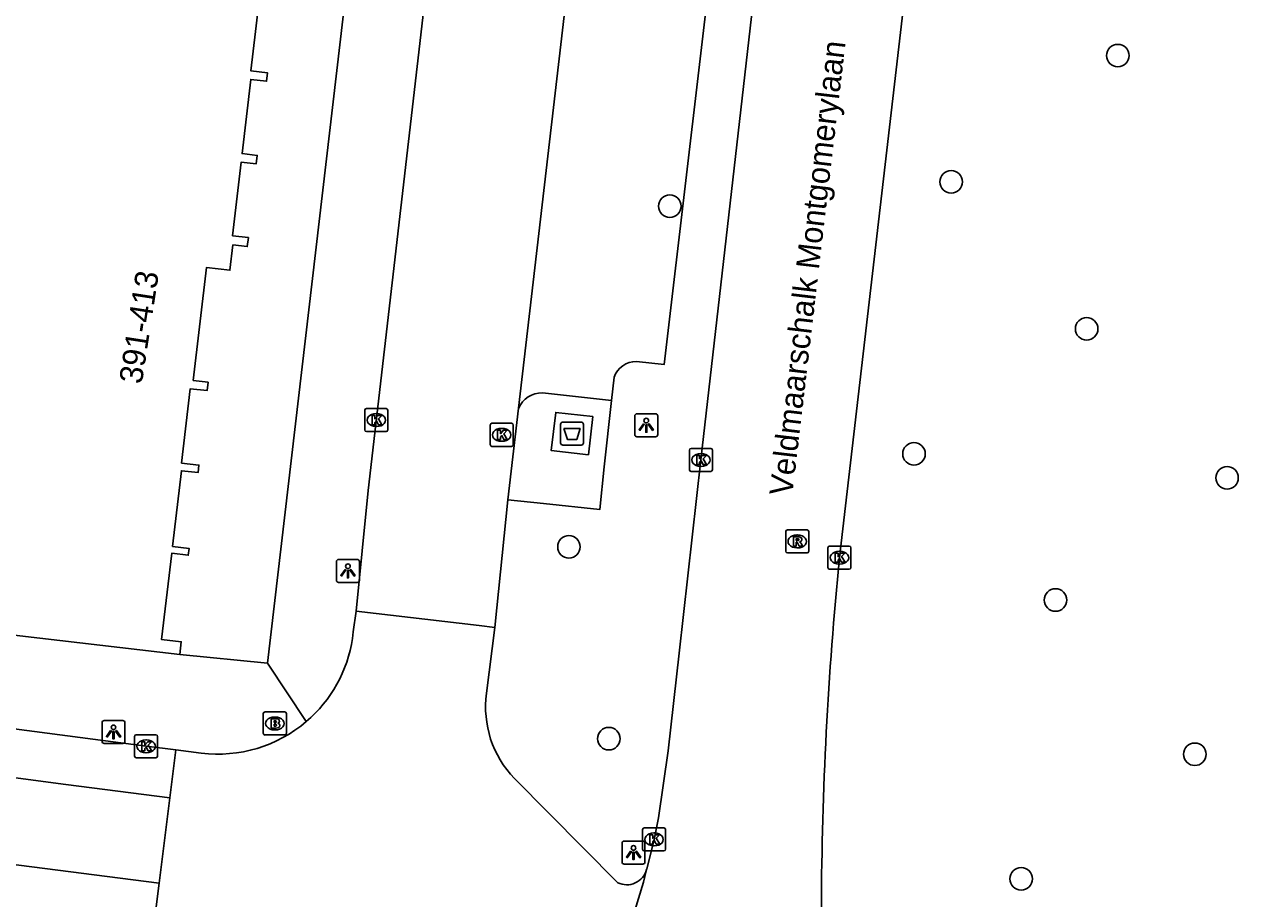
# Model space of a CAD drawing. Extents: x 160861 to 161308, y 384024 to 384878.
# Drawn here: x 161210.2 to 161263.2, y 384371.9 to 384409.8 of the extents above; entities that cross this region are included whole.
import ezdxf

# ---------------------------------------------------------------- set-up
doc = ezdxf.new("R2010")
doc.units = 0
for name, color, linetype in [('IMGEO_Afval_apart_plaats', 7, 'Continuous'), ('IMGEO_Boom', 7, 'Continuous'), ('IMGEO_Brandkraan', 7, 'Continuous'), ('IMGEO_Kolk', 7, 'Continuous'), ('IMGEO_Lichtpunt', 7, 'Continuous'), ('IMGEO_Openbare_ruimte_label', 7, 'Continuous'), ('IMGEO_Pand', 7, 'Continuous'), ('IMGEO_Pand_nummerreeks', 7, 'Continuous'), ('IMGEO_Parkeervlak_open', 7, 'Continuous'), ('IMGEO_Rijbaan_lokaal_gesloten', 7, 'Continuous'), ('IMGEO_Rijbaan_lokaal_open', 7, 'Continuous'), ('IMGEO_Rioolput', 7, 'Continuous'), ('IMGEO_Voetpad_gesloten', 7, 'Continuous'), ('IMGEO_Voetpad_open', 7, 'Continuous')]:
    doc.layers.add(name, color=color, linetype=linetype)

msp = doc.modelspace()

# ---------------------------------------------------------------- linework, layer by layer
at = {"layer": 'IMGEO_Afval_apart_plaats'}
for p, q in [((161233.508, 384391.639), (161233.508, 384392.439)), ((161233.508, 384392.439), (161233.508, 384391.639)), ((161233.608, 384392.539), (161234.398, 384392.539)), ((161234.398, 384392.539), (161233.608, 384392.539)), ((161234.498, 384392.439), (161234.498, 384391.639)), ((161234.498, 384391.639), (161234.498, 384392.439)), ((161234.398, 384391.539), (161233.608, 384391.539)), ((161233.608, 384391.539), (161234.398, 384391.539))]:
    msp.add_line(p, q, dxfattribs=at)
msp.add_lwpolyline([(161233.651, 384392.253), (161234.355, 384392.253), (161234.206, 384391.783), (161233.8, 384391.783), (161233.651, 384392.253)], dxfattribs=at)
for centre, start, end in [((161233.608, 384392.439), 90, 180), ((161233.608, 384392.439), 90, 180), ((161234.398, 384392.439), 0, 90), ((161234.398, 384392.439), 360, 90), ((161233.608, 384391.639), 180, 270), ((161233.608, 384391.639), 180, 270), ((161234.398, 384391.639), 270, 0), ((161234.398, 384391.639), 270, 0)]:
    msp.add_arc(centre, 0.1, start, end, dxfattribs=at)
at = {"layer": 'IMGEO_Boom'}
for centre in [(161257.691, 384408.433), (161250.463, 384402.957), (161238.248, 384401.904), (161256.341, 384396.581), (161248.846, 384391.156), (161262.436, 384390.118), (161233.869, 384387.13), (161254.991, 384384.819), (161235.599, 384378.804), (161261.035, 384378.127), (161253.501, 384372.726)]:
    msp.add_circle(centre, 0.489, dxfattribs=at)
at = {"layer": 'IMGEO_Brandkraan'}
for p, q in [((161220.602, 384379.038), (161220.602, 384379.89)), ((161220.677, 384379.964), (161221.529, 384379.964)), ((161221.09, 384379.744), (161221.115, 384379.744)), ((161221.603, 384379.89), (161221.603, 384379.038)), ((161221.113, 384379.184), (161221.088, 384379.184)), ((161221.529, 384378.964), (161220.677, 384378.964))]:
    msp.add_line(p, q, dxfattribs=at)
for points in [[(161220.602, 384379.038), (161220.602, 384379.89)], [(161220.677, 384379.964), (161221.529, 384379.964)], [(161220.95, 384379.664), (161220.95, 384379.264), (161221.163, 384379.264)], [(161221.181, 384379.664), (161220.95, 384379.664)], [(161221.129, 384379.583), (161221.075, 384379.583), (161221.075, 384379.507)], [(161221.603, 384379.89), (161221.603, 384379.038)], [(161221.075, 384379.507), (161221.128, 384379.507)], [(161221.137, 384379.431), (161221.075, 384379.431), (161221.075, 384379.35)], [(161221.075, 384379.35), (161221.137, 384379.35)], [(161221.529, 384378.964), (161220.677, 384378.964)]]:
    msp.add_lwpolyline(points, dxfattribs=at)
for centre, radius, start, end in [((161220.679, 384379.888), 0.0765, 91.552, 178.448), ((161220.679, 384379.888), 0.0765, 91.552, 178.448), ((161221.13, 384379.545), 0.0379, 267.8285, 90.9355), ((161221.185, 384379.519), 0.145, 59.4692, 91.5367), ((161221.21, 384379.566), 0.0922, 285.5137, 58.1501), ((161221.527, 384379.888), 0.0765, 1.552, 88.448), ((161221.527, 384379.888), 0.0765, 1.552, 88.448), ((161220.679, 384379.04), 0.0765, 181.552, 268.448), ((161220.679, 384379.04), 0.0765, 181.552, 268.448), ((161221.138, 384379.39), 0.0404, 269.8759, 90.5077), ((161221.169, 384379.515), 0.251, 268.6676, 293.5347), ((161221.215, 384379.374), 0.105, 301.3115, 78.989), ((161221.527, 384379.04), 0.0765, 271.552, 358.448), ((161221.527, 384379.04), 0.0765, 271.552, 358.448)]:
    msp.add_arc(centre, radius, start, end, dxfattribs=at)
for centre, major_axis, ratio, start_param, end_param in [((161221.089, 384379.464), (-0.387, 0.002), 0.722429, 4.712389, 7.853982), ((161221.114, 384379.464), (-0.39, 0.002), 0.717154, 1.570796, 4.712389)]:
    msp.add_ellipse(centre, major_axis=major_axis, ratio=ratio, start_param=start_param, end_param=end_param, dxfattribs=at)
at = {"layer": 'IMGEO_Kolk'}
for p, q in [((161225.006, 384392.198), (161225.006, 384393.05)), ((161225.081, 384393.124), (161225.933, 384393.124)), ((161225.494, 384392.904), (161225.519, 384392.904)), ((161226.007, 384393.05), (161226.007, 384392.198)), ((161225.517, 384392.344), (161225.492, 384392.344)), ((161230.449, 384391.558), (161230.449, 384392.41)), ((161230.524, 384392.484), (161231.376, 384392.484)), ((161230.937, 384392.264), (161230.962, 384392.264)), ((161231.45, 384392.41), (161231.45, 384391.558)), ((161225.933, 384392.124), (161225.081, 384392.124)), ((161230.96, 384391.704), (161230.935, 384391.704)), ((161231.376, 384391.484), (161230.524, 384391.484)), ((161239.099, 384390.468), (161239.099, 384391.32)), ((161239.174, 384391.394), (161240.026, 384391.394)), ((161239.587, 384391.174), (161239.612, 384391.174)), ((161240.1, 384391.32), (161240.1, 384390.468)), ((161240.026, 384390.394), (161239.174, 384390.394)), ((161239.61, 384390.614), (161239.585, 384390.614)), ((161245.11, 384386.23), (161245.11, 384387.082)), ((161245.185, 384387.156), (161246.037, 384387.156)), ((161246.111, 384387.082), (161246.111, 384386.23)), ((161245.598, 384386.936), (161245.623, 384386.936)), ((161246.037, 384386.156), (161245.185, 384386.156)), ((161245.621, 384386.376), (161245.596, 384386.376)), ((161215.013, 384378.048), (161215.013, 384378.9)), ((161215.088, 384378.974), (161215.94, 384378.974)), ((161215.501, 384378.754), (161215.526, 384378.754)), ((161216.014, 384378.9), (161216.014, 384378.048)), ((161215.94, 384377.974), (161215.088, 384377.974)), ((161215.524, 384378.194), (161215.499, 384378.194)), ((161237.062, 384374.008), (161237.062, 384374.86)), ((161237.137, 384374.934), (161237.989, 384374.934)), ((161238.063, 384374.86), (161238.063, 384374.008)), ((161237.55, 384374.714), (161237.575, 384374.714)), ((161237.989, 384373.934), (161237.137, 384373.934)), ((161237.573, 384374.154), (161237.548, 384374.154))]:
    msp.add_line(p, q, dxfattribs=at)
for points in [[(161225.006, 384392.198), (161225.006, 384393.05)], [(161225.081, 384393.124), (161225.933, 384393.124)], [(161225.327, 384392.824), (161225.45, 384392.824), (161225.45, 384392.673), (161225.58, 384392.824), (161225.744, 384392.824), (161225.598, 384392.673), (161225.751, 384392.424), (161225.599, 384392.424), (161225.514, 384392.588), (161225.45, 384392.521), (161225.45, 384392.424), (161225.327, 384392.424), (161225.327, 384392.824)], [(161226.007, 384393.05), (161226.007, 384392.198)], [(161230.449, 384391.558), (161230.449, 384392.41)], [(161230.524, 384392.484), (161231.376, 384392.484)], [(161231.45, 384392.41), (161231.45, 384391.558)], [(161225.933, 384392.124), (161225.081, 384392.124)], [(161230.77, 384392.184), (161230.893, 384392.184), (161230.893, 384392.033), (161231.023, 384392.184), (161231.187, 384392.184), (161231.041, 384392.033), (161231.194, 384391.784), (161231.042, 384391.784), (161230.957, 384391.948), (161230.893, 384391.881), (161230.893, 384391.784), (161230.77, 384391.784), (161230.77, 384392.184)], [(161231.376, 384391.484), (161230.524, 384391.484)], [(161239.099, 384390.468), (161239.099, 384391.32)], [(161239.174, 384391.394), (161240.026, 384391.394)], [(161240.1, 384391.32), (161240.1, 384390.468)], [(161239.42, 384391.094), (161239.543, 384391.094), (161239.543, 384390.943), (161239.673, 384391.094), (161239.837, 384391.094), (161239.691, 384390.943), (161239.844, 384390.694), (161239.692, 384390.694), (161239.607, 384390.858), (161239.543, 384390.791), (161239.543, 384390.694), (161239.42, 384390.694), (161239.42, 384391.094)], [(161240.026, 384390.394), (161239.174, 384390.394)], [(161245.11, 384386.23), (161245.11, 384387.082)], [(161245.185, 384387.156), (161246.037, 384387.156)], [(161246.111, 384387.082), (161246.111, 384386.23)], [(161245.431, 384386.856), (161245.554, 384386.856), (161245.554, 384386.705), (161245.684, 384386.856), (161245.848, 384386.856), (161245.702, 384386.705), (161245.855, 384386.456), (161245.703, 384386.456), (161245.618, 384386.62), (161245.554, 384386.553), (161245.554, 384386.456), (161245.431, 384386.456), (161245.431, 384386.856)], [(161246.037, 384386.156), (161245.185, 384386.156)], [(161215.013, 384378.048), (161215.013, 384378.9)], [(161215.088, 384378.974), (161215.94, 384378.974)], [(161215.334, 384378.674), (161215.457, 384378.674), (161215.457, 384378.523), (161215.587, 384378.674), (161215.751, 384378.674), (161215.605, 384378.523), (161215.758, 384378.274), (161215.606, 384378.274), (161215.521, 384378.438), (161215.457, 384378.371), (161215.457, 384378.274), (161215.334, 384378.274), (161215.334, 384378.674)], [(161216.014, 384378.9), (161216.014, 384378.048)], [(161215.94, 384377.974), (161215.088, 384377.974)], [(161237.062, 384374.008), (161237.062, 384374.86)], [(161237.137, 384374.934), (161237.989, 384374.934)], [(161238.063, 384374.86), (161238.063, 384374.008)], [(161237.383, 384374.634), (161237.506, 384374.634), (161237.506, 384374.483), (161237.636, 384374.634), (161237.8, 384374.634), (161237.654, 384374.483), (161237.807, 384374.234), (161237.655, 384374.234), (161237.57, 384374.398), (161237.506, 384374.331), (161237.506, 384374.234), (161237.383, 384374.234), (161237.383, 384374.634)], [(161237.989, 384373.934), (161237.137, 384373.934)]]:
    msp.add_lwpolyline(points, dxfattribs=at)
for centre, start, end in [((161225.083, 384393.048), 91.552, 178.448), ((161225.083, 384393.048), 91.552, 178.448), ((161225.931, 384393.048), 1.552, 88.448), ((161225.931, 384393.048), 1.552, 88.448), ((161230.526, 384392.408), 91.552, 178.448), ((161230.526, 384392.408), 91.552, 178.448), ((161231.374, 384392.408), 1.552, 88.448), ((161231.374, 384392.408), 1.552, 88.448), ((161225.083, 384392.2), 181.552, 268.448), ((161225.083, 384392.2), 181.552, 268.448), ((161225.931, 384392.2), 271.552, 358.448), ((161225.931, 384392.2), 271.552, 358.448), ((161230.526, 384391.56), 181.552, 268.448), ((161230.526, 384391.56), 181.552, 268.448), ((161231.374, 384391.56), 271.552, 358.448), ((161231.374, 384391.56), 271.552, 358.448), ((161239.176, 384391.318), 91.552, 178.448), ((161239.176, 384391.318), 91.552, 178.448), ((161240.024, 384391.318), 1.552, 88.448), ((161240.024, 384391.318), 1.552, 88.448), ((161239.176, 384390.47), 181.552, 268.448), ((161239.176, 384390.47), 181.552, 268.448), ((161240.024, 384390.47), 271.552, 358.448), ((161240.024, 384390.47), 271.552, 358.448), ((161245.187, 384387.08), 91.552, 178.448), ((161245.187, 384387.08), 91.552, 178.448), ((161246.035, 384387.08), 1.552, 88.448), ((161246.035, 384387.08), 1.552, 88.448), ((161245.187, 384386.232), 181.552, 268.448), ((161245.187, 384386.232), 181.552, 268.448), ((161246.035, 384386.232), 271.552, 358.448), ((161246.035, 384386.232), 271.552, 358.448), ((161215.09, 384378.898), 91.552, 178.448), ((161215.09, 384378.898), 91.552, 178.448), ((161215.938, 384378.898), 1.552, 88.448), ((161215.938, 384378.898), 1.552, 88.448), ((161215.09, 384378.05), 181.552, 268.448), ((161215.09, 384378.05), 181.552, 268.448), ((161215.938, 384378.05), 271.552, 358.448), ((161215.938, 384378.05), 271.552, 358.448), ((161237.139, 384374.858), 91.552, 178.448), ((161237.139, 384374.858), 91.552, 178.448), ((161237.987, 384374.858), 1.552, 88.448), ((161237.987, 384374.858), 1.552, 88.448), ((161237.139, 384374.01), 181.552, 268.448), ((161237.139, 384374.01), 181.552, 268.448), ((161237.987, 384374.01), 271.552, 358.448), ((161237.987, 384374.01), 271.552, 358.448)]:
    msp.add_arc(centre, 0.0765, start, end, dxfattribs=at)
for centre, major_axis, ratio, start_param, end_param in [((161225.493, 384392.624), (-0.387, 0.002), 0.722429, 4.712389, 7.853982), ((161225.518, 384392.624), (-0.39, 0.002), 0.717154, 1.570796, 4.712389), ((161230.936, 384391.984), (-0.387, 0.002), 0.722429, 4.712389, 7.853982), ((161230.961, 384391.984), (-0.39, 0.002), 0.717154, 1.570796, 4.712389), ((161239.586, 384390.894), (-0.387, 0.002), 0.722429, 4.712389, 7.853982), ((161239.611, 384390.894), (-0.39, 0.002), 0.717154, 1.570796, 4.712389), ((161245.597, 384386.656), (-0.387, 0.002), 0.722429, 4.712389, 7.853982), ((161245.622, 384386.656), (-0.39, 0.002), 0.717154, 1.570796, 4.712389), ((161215.5, 384378.474), (-0.387, 0.002), 0.722429, 4.712389, 7.853982), ((161215.525, 384378.474), (-0.39, 0.002), 0.717154, 1.570796, 4.712389), ((161237.549, 384374.434), (-0.387, 0.002), 0.722429, 4.712389, 7.853982), ((161237.574, 384374.434), (-0.39, 0.002), 0.717154, 1.570796, 4.712389)]:
    msp.add_ellipse(centre, major_axis=major_axis, ratio=ratio, start_param=start_param, end_param=end_param, dxfattribs=at)
at = {"layer": 'IMGEO_Lichtpunt'}
for p, q in [((161236.727, 384392.804), (161236.727, 384391.997)), ((161236.727, 384392.804), (161236.727, 384391.997)), ((161237.629, 384392.899), (161236.821, 384392.899)), ((161237.629, 384392.899), (161236.821, 384392.899)), ((161237.723, 384391.997), (161237.723, 384392.804)), ((161237.723, 384391.997), (161237.723, 384392.804)), ((161236.821, 384391.903), (161237.629, 384391.903)), ((161236.821, 384391.903), (161237.629, 384391.903)), ((161223.775, 384386.485), (161223.775, 384385.678)), ((161223.775, 384386.485), (161223.775, 384385.678)), ((161224.677, 384386.58), (161223.869, 384386.58)), ((161224.677, 384386.58), (161223.869, 384386.58)), ((161224.771, 384385.678), (161224.771, 384386.485)), ((161224.771, 384385.678), (161224.771, 384386.485)), ((161223.869, 384385.584), (161224.677, 384385.584)), ((161223.869, 384385.584), (161224.677, 384385.584)), ((161214.503, 384379.592), (161213.695, 384379.592)), ((161214.503, 384379.592), (161213.695, 384379.592)), ((161213.601, 384379.497), (161213.601, 384378.69)), ((161213.601, 384379.497), (161213.601, 384378.69)), ((161214.597, 384378.69), (161214.597, 384379.497)), ((161214.597, 384378.69), (161214.597, 384379.497)), ((161213.695, 384378.596), (161214.503, 384378.596)), ((161213.695, 384378.596), (161214.503, 384378.596)), ((161236.173, 384374.267), (161236.173, 384373.46)), ((161236.173, 384374.267), (161236.173, 384373.46)), ((161237.075, 384374.362), (161236.267, 384374.362)), ((161237.075, 384374.362), (161236.267, 384374.362)), ((161237.169, 384373.46), (161237.169, 384374.267)), ((161237.169, 384373.46), (161237.169, 384374.267)), ((161236.267, 384373.366), (161237.075, 384373.366)), ((161236.267, 384373.366), (161237.075, 384373.366))]:
    msp.add_line(p, q, dxfattribs=at)
for points in [[(161237.101, 384392.468), (161237.14, 384392.44), (161236.952, 384392.178), (161236.914, 384392.205), (161237.101, 384392.468)], [(161237.203, 384392.42), (161237.25, 384392.42), (161237.25, 384392.098), (161237.203, 384392.098), (161237.203, 384392.42)], [(161237.313, 384392.44), (161237.351, 384392.467), (161237.538, 384392.205), (161237.499, 384392.177), (161237.313, 384392.44)], [(161224.149, 384386.149), (161224.188, 384386.121), (161224, 384385.859), (161223.962, 384385.886), (161224.149, 384386.149)], [(161224.251, 384386.101), (161224.298, 384386.101), (161224.298, 384385.779), (161224.251, 384385.779), (161224.251, 384386.101)], [(161224.361, 384386.121), (161224.399, 384386.148), (161224.586, 384385.886), (161224.547, 384385.858), (161224.361, 384386.121)], [(161213.975, 384379.161), (161214.014, 384379.133), (161213.826, 384378.871), (161213.788, 384378.898), (161213.975, 384379.161)], [(161214.077, 384379.113), (161214.124, 384379.113), (161214.124, 384378.791), (161214.077, 384378.791), (161214.077, 384379.113)], [(161214.187, 384379.133), (161214.225, 384379.16), (161214.412, 384378.898), (161214.373, 384378.87), (161214.187, 384379.133)], [(161236.547, 384373.931), (161236.586, 384373.903), (161236.398, 384373.641), (161236.36, 384373.668), (161236.547, 384373.931)], [(161236.649, 384373.883), (161236.696, 384373.883), (161236.696, 384373.561), (161236.649, 384373.561), (161236.649, 384373.883)], [(161236.759, 384373.903), (161236.797, 384373.93), (161236.984, 384373.668), (161236.945, 384373.64), (161236.759, 384373.903)]]:
    msp.add_lwpolyline(points, dxfattribs=at)
for centre in [(161237.226, 384392.602), (161224.274, 384386.283), (161214.1, 384379.295), (161236.672, 384374.065)]:
    msp.add_circle(centre, 0.0994, dxfattribs=at)
for centre, start, end in [((161236.821, 384392.804), 90, 180), ((161236.821, 384392.804), 90, 180), ((161237.629, 384392.804), 0, 90), ((161237.629, 384392.804), 0, 90), ((161236.821, 384391.997), 180, 270), ((161236.821, 384391.997), 180, 270), ((161237.629, 384391.997), 270, 0), ((161237.629, 384391.997), 270, 360), ((161223.869, 384386.485), 90, 180), ((161223.869, 384386.485), 90, 180), ((161224.677, 384386.485), 0, 90), ((161224.677, 384386.485), 0, 90), ((161223.869, 384385.678), 180, 270), ((161223.869, 384385.678), 180, 270), ((161224.677, 384385.678), 270, 0), ((161224.677, 384385.678), 270, 360), ((161213.695, 384379.497), 90, 180), ((161213.695, 384379.497), 90, 180), ((161214.503, 384379.497), 0, 90), ((161214.503, 384379.497), 0, 90), ((161213.695, 384378.69), 180, 270), ((161213.695, 384378.69), 180, 270), ((161214.503, 384378.69), 270, 0), ((161214.503, 384378.69), 270, 360), ((161236.267, 384374.267), 90, 180), ((161236.267, 384374.267), 90, 180), ((161237.075, 384374.267), 0, 90), ((161237.075, 384374.267), 0, 90), ((161236.267, 384373.46), 180, 270), ((161236.267, 384373.46), 180, 270), ((161237.075, 384373.46), 270, 0), ((161237.075, 384373.46), 270, 360)]:
    msp.add_arc(centre, 0.0946, start, end, dxfattribs=at)
at = {"layer": 'IMGEO_Pand'}
for points in [[(161216.979, 384382.453), (161217.043, 384383.005), (161216.188, 384383.105), (161216.625, 384386.847), (161217.347, 384386.763), (161217.381, 384387.06), (161216.662, 384387.144), (161217.045, 384390.428), (161217.77, 384390.343), (161217.808, 384390.67), (161217.054, 384390.758), (161217.431, 384393.986), (161218.161, 384393.901), (161218.204, 384394.266), (161217.564, 384394.341), (161218.136, 384399.242), (161219.154, 384399.124), (161219.282, 384400.223), (161219.906, 384400.15), (161219.952, 384400.539), (161219.27, 384400.618), (161219.643, 384403.815), (161220.293, 384403.739), (161220.336, 384404.105), (161219.678, 384404.182), (161220.054, 384407.402), (161220.746, 384407.321), (161220.788, 384407.683), (161220.066, 384407.767), (161220.495, 384411.447)], [(161216.979, 384382.453), (161203.696, 384384.003)]]:
    msp.add_lwpolyline(points, dxfattribs=at)
at = {"layer": 'IMGEO_Parkeervlak_open'}
for points in [[(161236.799, 384395.17), (161238.006, 384395.04), (161238.15, 384396.266), (161250.377, 384500), (161251.596, 384511.132), (161256.785, 384556.041), (161250.737, 384556.74)], [(161235.716, 384393.474), (161235.825, 384394.48)]]:
    msp.add_lwpolyline(points, dxfattribs=at)
msp.add_arc((161236.807, 384394.127), 1.043, 90.4238, 160.2052, dxfattribs=at)
at = {"layer": 'IMGEO_Rijbaan_lokaal_gesloten'}
for points in [[(161261.966, 384583.337), (161261.579, 384580.114), (161259.33, 384560.777), (161257.178, 384542.439), (161254.83, 384522.177), (161252.438, 384501.823), (161250.03, 384480.998), (161247.876, 384462.682), (161246.021, 384446.828), (161243.88, 384428.499), (161241.912, 384411.162), (161239.6, 384390.894), (161238.653, 384382.516), (161238.178, 384378.283), (161237.763, 384375.367), (161237.563, 384374.434), (161237.479, 384374.076), (161237.25, 384373.157), (161237.241, 384373.124)], [(161245.611, 384386.656), (161254.88, 384466.32), (161259.354, 384504.899), (161266.33, 384564.879), (161266.816, 384568.826), (161267.446, 384572.759), (161268.148, 384576.401), (161269.166, 384580.645)]]:
    msp.add_lwpolyline(points, dxfattribs=at)
msp.add_arc((161406.986, 384370.689), 162.163, 174.34924, 179.71407, dxfattribs=at)
at = {"layer": 'IMGEO_Rijbaan_lokaal_open'}
for points in [[(161250.737, 384556.74), (161231.686, 384393.141)], [(161224.63, 384384.341), (161225.155, 384389.562), (161231.826, 384447.259), (161235.532, 384478.284), (161236.635, 384487.009), (161236.821, 384488.628)], [(161231.223, 384389.168), (161231.686, 384393.141)], [(161230.652, 384383.631), (161231.223, 384389.168)], [(161224.471, 384383.156), (161224.506, 384383.434), (161224.63, 384384.341)], [(161230.652, 384383.631), (161229.978, 384383.71), (161224.63, 384384.341)], [(161230.293, 384380.775), (161230.652, 384383.631)], [(161216.546, 384376.235), (161212.028, 384376.813), (161206.14, 384377.597), (161201.287, 384378.204), (161201.373, 384380.217), (161201.379, 384380.358)], [(161216.809, 384378.322), (161216.546, 384376.235)], [(161216.809, 384378.322), (161217.908, 384378.181)], [(161235.986, 384372.555), (161231.499, 384377.079)], [(161216.078, 384372.531), (161216.546, 384376.235)], [(161200.728, 384374.476), (161203.322, 384374.176), (161216.078, 384372.531)], [(161237.241, 384373.124), (161237.099, 384372.576), (161236.892, 384371.866), (161236.493, 384370.578), (161234.113, 384363.625)], [(161216.078, 384372.531), (161215.832, 384370.582)]]:
    msp.add_lwpolyline(points, dxfattribs=at)
for centre, radius, start, end in [((161218.641, 384384.029), 5.895, 310.4413, 351.4791), ((161234.687, 384380.164), 4.436, 172.0808, 224.0621), ((161218.642, 384384.03), 5.895, 262.8474, 310.4334), ((161236.375, 384373.366), 0.9, 244.397, 344.3808)]:
    msp.add_arc(centre, radius, start, end, dxfattribs=at)
at = {"layer": 'IMGEO_Rioolput'}
for p, q in [((161243.278, 384386.933), (161243.278, 384387.785)), ((161243.353, 384387.859), (161244.205, 384387.859)), ((161243.766, 384387.639), (161243.791, 384387.639)), ((161244.279, 384387.785), (161244.279, 384386.933)), ((161243.789, 384387.079), (161243.764, 384387.079)), ((161244.205, 384386.859), (161243.353, 384386.859))]:
    msp.add_line(p, q, dxfattribs=at)
for points in [[(161243.278, 384386.933), (161243.278, 384387.785)], [(161243.353, 384387.859), (161244.205, 384387.859)], [(161243.867, 384387.557), (161243.615, 384387.559), (161243.615, 384387.159)], [(161243.793, 384387.478), (161243.739, 384387.478), (161243.739, 384387.397)], [(161244.279, 384387.785), (161244.279, 384386.933)], [(161243.615, 384387.159), (161243.739, 384387.159), (161243.739, 384387.321), (161243.75, 384387.321)], [(161243.739, 384387.397), (161243.791, 384387.397)], [(161243.797, 384387.292), (161243.868, 384387.159), (161244.008, 384387.159), (161243.943, 384387.285)], [(161244.205, 384386.859), (161243.353, 384386.859)]]:
    msp.add_lwpolyline(points, dxfattribs=at)
for centre, radius, start, end in [((161243.355, 384387.783), 0.0765, 91.552, 178.448), ((161243.355, 384387.783), 0.0765, 91.552, 178.448), ((161243.799, 384387.382), 0.0964, 77.0061, 93.1865), ((161243.813, 384387.439), 0.0378, 276.6634, 79.6772), ((161243.866, 384387.447), 0.109, 350.3612, 89.416), ((161244.203, 384387.783), 0.0765, 1.552, 88.448), ((161244.203, 384387.783), 0.0765, 1.552, 88.448), ((161243.749, 384387.268), 0.0533, 26.0293, 88.6989), ((161243.775, 384387.586), 0.19, 274.7715, 282.9687), ((161243.864, 384387.447), 0.112, 277.5842, 350.9817), ((161243.848, 384387.232), 0.108, 29.5134, 73.7905), ((161243.355, 384386.935), 0.0765, 181.552, 268.448), ((161243.355, 384386.935), 0.0765, 181.552, 268.448), ((161244.203, 384386.935), 0.0765, 271.552, 358.448), ((161244.203, 384386.935), 0.0765, 271.552, 358.448)]:
    msp.add_arc(centre, radius, start, end, dxfattribs=at)
for centre, major_axis, ratio, start_param, end_param in [((161243.765, 384387.359), (-0.387, 0.002), 0.722429, 4.712389, 7.853982), ((161243.79, 384387.359), (-0.39, 0.002), 0.717154, 1.570796, 4.712389)]:
    msp.add_ellipse(centre, major_axis=major_axis, ratio=ratio, start_param=start_param, end_param=end_param, dxfattribs=at)
at = {"layer": 'IMGEO_Voetpad_gesloten'}
msp.add_lwpolyline([(161234.903, 384392.774), (161233.293, 384392.959), (161233.103, 384391.304), (161234.713, 384391.119), (161234.903, 384392.774)], dxfattribs=at)
at = {"layer": 'IMGEO_Voetpad_open'}
for points in [[(161233.475, 384490.485), (161220.779, 384382.081)], [(161231.223, 384389.168), (161232.763, 384389.003), (161235.203, 384388.741), (161235.404, 384390.594), (161235.716, 384393.474)], [(161232.716, 384393.799), (161235.716, 384393.474)], [(161220.779, 384382.081), (161216.979, 384382.453)], [(161222.465, 384379.543), (161220.779, 384382.081)], [(161201.379, 384380.358), (161202.059, 384380.267), (161204.594, 384379.908), (161215.514, 384378.474), (161216.809, 384378.322)]]:
    msp.add_lwpolyline(points, dxfattribs=at)
msp.add_arc((161232.68, 384392.72), 1.079, 88.092, 157.0517, dxfattribs=at)

# ---------------------------------------------------------------- texts
at = {"layer": 'IMGEO_Openbare_ruimte_label'}
msp.add_text('Veldmaarschalk Montgomerylaan', height=1, rotation=83.2801, dxfattribs=at).set_placement((161243.558, 384389.307))
at = {"layer": 'IMGEO_Pand_nummerreeks'}
msp.add_text('391-413', height=1, rotation=81.2424, dxfattribs=at).set_placement((161215.326, 384394.159))

doc.saveas('drawing.dxf')
